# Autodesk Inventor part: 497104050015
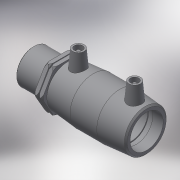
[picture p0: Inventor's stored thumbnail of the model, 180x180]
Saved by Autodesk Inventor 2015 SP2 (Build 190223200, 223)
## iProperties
Created: 2017-06
Part Number: 497104050015
Material: Generic
Description: PLASSON PE MALE TRANSITION COUPLER 50-1.1/2"
Document SubType Name: Modeling
Designer: KIM
Mass: 55.0731 g
Surface Area: 148.067 cm^2
Volume: 55.0731 cm^3
Density: 1 g/cm^3
Appearance: Default
Author: KIM
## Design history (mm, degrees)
derived "497104.ipt"
feature "Solid1::497104.ipt"
tag "TaggingFeature1"
body "Solid1"
other parameters: "d0" = 101, "d2" = 67, "d3" = 49, "d4" = 33.66667, "d5" = 60.3, "d6" = 47.5, "d8" = 168 deg, "d10" = 19.6, "d11" = 6.53333, "d29" = 51, "d30" = 14, "d31" = 35.35, "d34" = 5 deg, "d41" = 4, "d42" = 14, "d43" = 0, "d48" = 3, "d49" = 0, "d57" = 38, "d58" = 41.91, "d59" = 33.528, "d60" = 36, "d61" = 58.674, "d62" = 0.8382, "d65" = 2.01, "d70" = 0.1, "d73" = 19.6, "d75" = 0, "d76" = 1, "d77" = 4.5, "d78" = 58.674, "L_" = 141, "L_2" = 49, "D_1" = 67, "A_" = 51, "d_2" = 12, "D_" = 38, "R_" = 41.91
